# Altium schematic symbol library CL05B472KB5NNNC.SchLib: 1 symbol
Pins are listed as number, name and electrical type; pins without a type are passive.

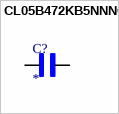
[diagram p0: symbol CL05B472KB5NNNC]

## CL05B472KB5NNNC
designator C?
4700 pF Â±10% 50V Ceramic Capacitor X7R 0402 (1005 Metric); MF: Samsung; MP: CL05B472KB5NNNC
footprint CAPC1005X55N
pins: 1, 2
